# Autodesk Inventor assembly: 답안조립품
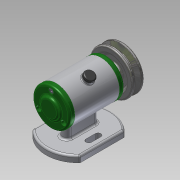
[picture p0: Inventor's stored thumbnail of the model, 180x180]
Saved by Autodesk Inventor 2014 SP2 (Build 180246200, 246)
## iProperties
Created: 2022-02
Part Number: 답안조립품
Document SubType Name: Assembly
Designer: 거성
Author: 거성
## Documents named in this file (14)
- C:\Users\거성\Desktop\720206V1001\답안조립품.iam
- C:\Users\거성\Desktop\720206V1001\본체.ipt
- C:\Users\거성\Desktop\720206V1001\베어링 6002.ipt
- C:\Users\거성\Desktop\720206V1001\앞커버.ipt
- C:\Users\거성\Desktop\720206V1001\뒤커버.ipt
- C:\Users\거성\Desktop\720206V1001\축.ipt
- C:\Users\거성\Desktop\720206V1001\V벨트풀리.ipt
- C:\Users\거성\Desktop\720206V1001\고무 캡.ipt
- C:\Users\거성\Desktop\720206V1001\너트 M8.ipt
- C:\Users\거성\Desktop\720206V1001\오일 실 15 x 25 x 7.ipt
- C:\Users\거성\Desktop\720206V1001\키 3 x 3 x 12.ipt
- C:\Users\거성\Desktop\720206V1001\스프링와셔 8.ipt
- C:\Users\거성\Desktop\720206V1001\평와셔 8 x 17.ipt
- C:\Users\거성\Desktop\720206V1001\볼트 M4 x 10.ipt
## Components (2 placed, 2 different names)
1. V벨트풀리:1 — 각도:2
2. 고무 캡:1
## Component patterns: 구성요소 패턴 1:2 (3 elements), 구성요소 패턴 1:3 (3 elements), 구성요소 패턴 1:4 (3 elements)
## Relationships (1: Angle 1)
- 각도:2 [Angle]: V벨트풀리:1
